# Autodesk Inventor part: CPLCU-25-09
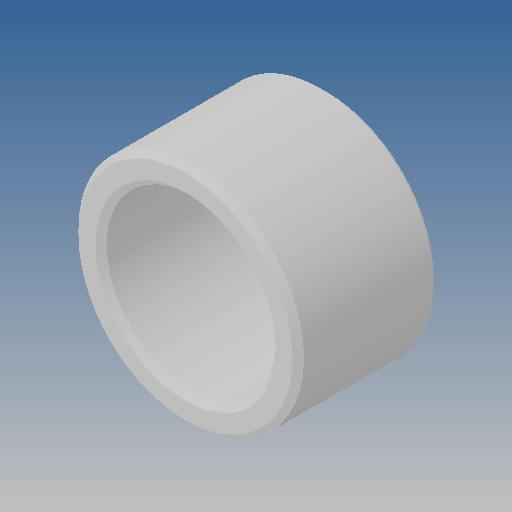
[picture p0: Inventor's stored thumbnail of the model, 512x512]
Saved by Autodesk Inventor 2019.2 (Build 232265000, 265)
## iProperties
Created: 2010-03
Part Number: CPLCU-25-09
Material: Ogólny
Document SubType Name: Modeling
Designer: CADENGINEERING4
Density: 1 g/cm^3
Appearance: Domyślna
Author: CADENGINEERING4
Revision Number: 1LAST_VERSION
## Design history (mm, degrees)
feature "Baza1"
node "Bryła1"
